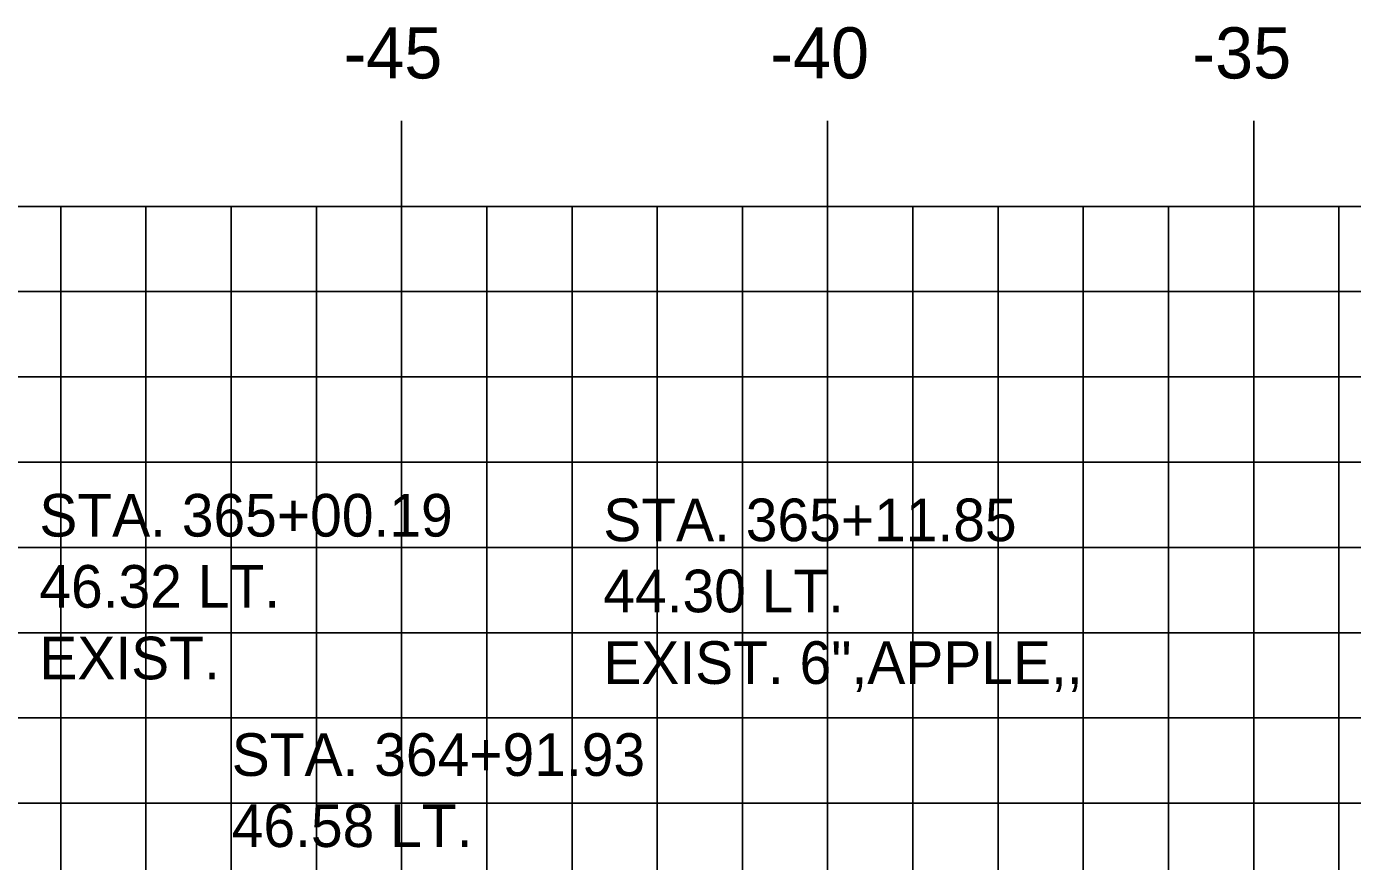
# Model space of a CAD drawing. Extents: x 1147190 to 1147360, y 608981 to 609091.
# Drawn here: x 1147223.54 to 1147239.1, y 609057.65 to 609067.44 of the extents above; entities that cross this region are included whole.
import ezdxf

# ---------------------------------------------------------------- set-up
doc = ezdxf.new("R2010")
doc.units = 0
for name, color, linetype in [('D_Text_Monospaced', 7, 'Continuous'), ('H_V ANNOTATION', 7, 'Continuous'), ('MAJOR', 7, 'Continuous'), ('MINOR', 7, 'Continuous')]:
    doc.layers.add(name, color=color, linetype=linetype)

msp = doc.modelspace()

# ---------------------------------------------------------------- linework, layer by layer
at = {"layer": 'MAJOR'}
for p, q in [((1147227.941, 609066.337), (1147227.941, 609065.335)), ((1147232.941, 609066.337), (1147232.941, 609065.335)), ((1147237.941, 609066.337), (1147237.941, 609065.335)), ((1147202.941, 609065.335), (1147342.941, 609065.335)), ((1147202.941, 609065.335), (1147342.941, 609065.335)), ((1147227.941, 609045.335), (1147227.941, 609065.335)), ((1147232.941, 609045.335), (1147232.941, 609065.335)), ((1147237.941, 609045.335), (1147237.941, 609065.335)), ((1147202.941, 609060.335), (1147342.941, 609060.335))]:
    msp.add_line(p, q, dxfattribs=at)
at = {"layer": 'MINOR'}
for p, q in [((1147223.941, 609045.335), (1147223.941, 609065.335)), ((1147224.941, 609045.335), (1147224.941, 609065.335)), ((1147225.941, 609045.335), (1147225.941, 609065.335)), ((1147226.941, 609045.335), (1147226.941, 609065.335)), ((1147228.941, 609045.335), (1147228.941, 609065.335)), ((1147229.941, 609045.335), (1147229.941, 609065.335)), ((1147230.941, 609045.335), (1147230.941, 609065.335)), ((1147231.941, 609045.335), (1147231.941, 609065.335)), ((1147233.941, 609045.335), (1147233.941, 609065.335)), ((1147234.941, 609045.335), (1147234.941, 609065.335)), ((1147235.941, 609045.335), (1147235.941, 609065.335)), ((1147236.941, 609045.335), (1147236.941, 609065.335)), ((1147238.941, 609045.335), (1147238.941, 609065.335)), ((1147202.941, 609064.335), (1147342.941, 609064.335)), ((1147202.941, 609063.335), (1147342.941, 609063.335)), ((1147202.941, 609062.335), (1147342.941, 609062.335)), ((1147202.941, 609061.335), (1147342.941, 609061.335)), ((1147202.941, 609059.335), (1147342.941, 609059.335)), ((1147202.941, 609058.335), (1147342.941, 609058.335))]:
    msp.add_line(p, q, dxfattribs=at)

# ---------------------------------------------------------------- texts
at = {"layer": 'D_Text_Monospaced'}
for s, height, p in [('STA. 365+00.19', 0.49998, (1147223.69, 609061.462)), ('STA. 365+11.85', 0.49998, (1147230.308, 609061.408)), ('46.32 LT.', 0.5, (1147223.69, 609060.628)), ('44.30 LT.', 0.5, (1147230.308, 609060.574)), ('EXIST. ', 0.5, (1147223.69, 609059.788)), ('EXIST. 6",APPLE,,', 0.49998, (1147230.308, 609059.734)), ('STA. 364+91.93', 0.49998, (1147225.948, 609058.655)), ('46.58 LT.', 0.5, (1147225.948, 609057.821))]:
    msp.add_text(s, height=height, dxfattribs=at).set_placement(p)
at = {"layer": 'H_V ANNOTATION'}
for s, p in [('-45', (1147227.259, 609066.835)), ('-40', (1147232.267, 609066.835)), ('-35', (1147237.221, 609066.835))]:
    msp.add_text(s, height=0.6, dxfattribs=at).set_placement(p)

doc.saveas('drawing.dxf')
